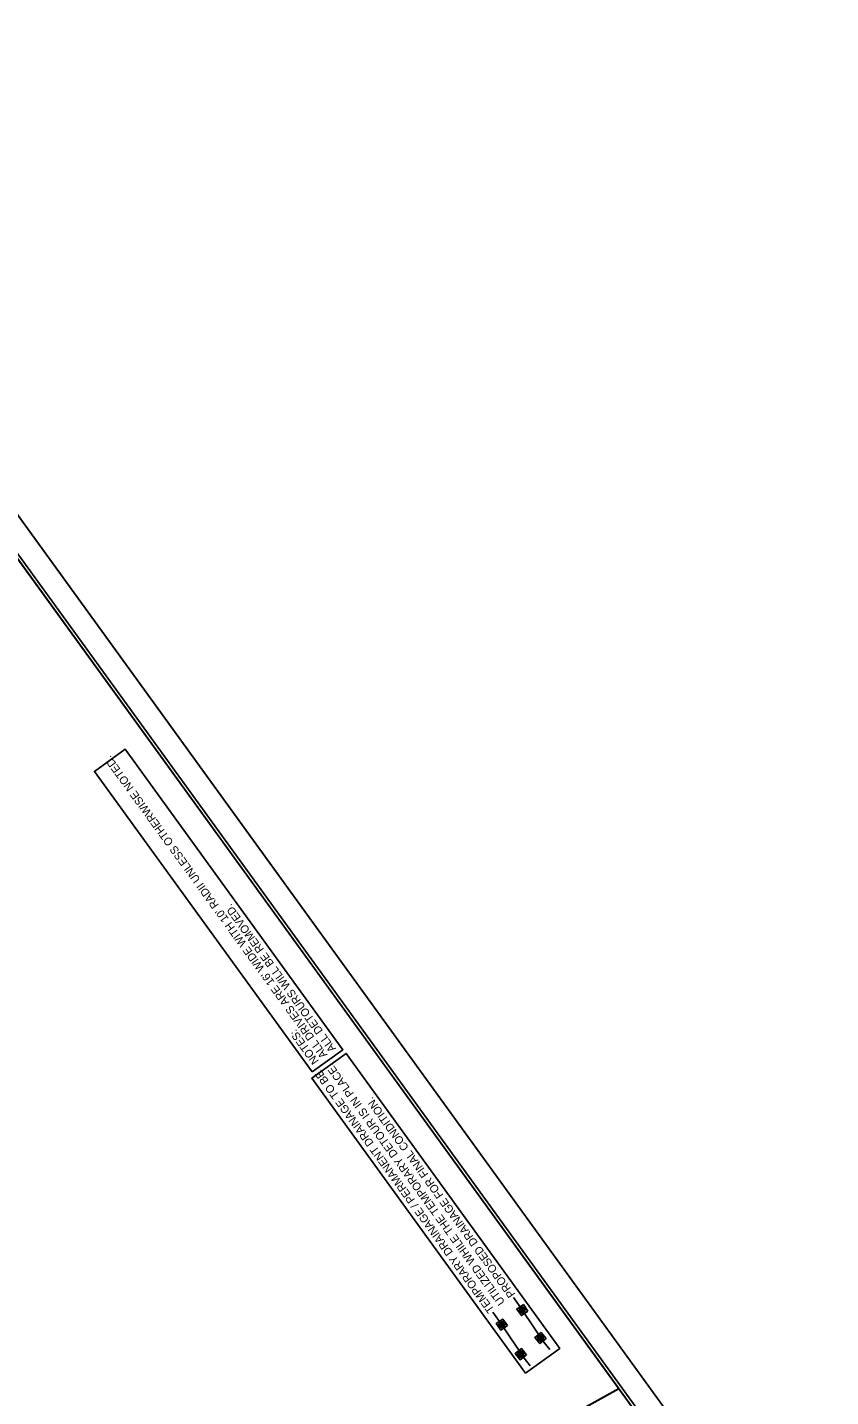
# Model space of a CAD drawing. Extents: x 474925 to 478950, y 494687 to 502905.
# Drawn here: x 476129 to 476832, y 501707 to 502905 of the extents above; entities that cross this region are included whole.
import ezdxf

# ---------------------------------------------------------------- set-up
doc = ezdxf.new("R2010")
doc.units = 0
for name, color, linetype in [('Old_Level_41', 7, 'Continuous'), ('Prop Drainage Structure CELL', 7, 'Continuous'), ('Prop DSN Text', 7, 'Continuous'), ('Prop Grid Mask', 7, 'Continuous'), ('Sheet Cutting Line CELL', 7, 'Continuous'), ('Sheet Data Field CELL', 7, 'Continuous'), ('Sheet Layout Plan Border', 7, 'Continuous'), ('Sheet Plan CELL', 7, 'Continuous'), ('Sheet Plan Layout CELL', 7, 'Continuous'), ('Sheet Plot Border Inside CELL', 7, 'Continuous'), ('Sheet Plot Border Outside CELL', 7, 'Continuous')]:
    doc.layers.add(name, color=color, linetype=linetype)

msp = doc.modelspace()

# ---------------------------------------------------------------- linework, layer by layer
at = {"layer": 'Old_Level_41'}
for p, q in [((476562.2, 501783.1), (476554.4, 501794)), ((476561.5, 501784), (476561.5, 501784)), ((476562.2, 501783.1), (476562.2, 501783.1)), ((476563.8, 501784.2), (476563.8, 501784.2)), ((476560.5, 501781.9), (476560.5, 501781.9)), ((476580.8, 501755.1), (476562.4, 501782.7)), ((476562.8, 501782.1), (476562.8, 501782.1)), ((476577.3, 501759.5), (476577.3, 501759.5)), ((476579.6, 501759.9), (476579.6, 501759.9)), ((476576.4, 501757.4), (476576.4, 501757.4)), ((476578, 501758.6), (476578, 501758.6)), ((476578.7, 501757.7), (476578.7, 501757.7)), ((476586.2, 501748.5), (476580.8, 501755.1))]:
    msp.add_line(p, q, dxfattribs=at)
for points in [[(476567, 501782.2), (476561.3, 501778.2), (476557.3, 501783.9), (476563, 501787.9)], [(476564.9, 501782.6), (476561.7, 501780.3), (476559.4, 501783.5), (476562.6, 501785.8)], [(476582.9, 501758.1), (476577.5, 501753.7), (476573.1, 501759.1), (476578.5, 501763.5)], [(476580.8, 501758.3), (476577.7, 501755.8), (476575.2, 501758.9), (476578.3, 501761.4)]]:
    msp.add_lwpolyline(points, close=True, dxfattribs=at)
for points in [[(476564.5, 501783.3), (476561.2, 501780.9), (476559.8, 501782.9), (476563.1, 501785.2), (476564.5, 501783.3)], [(476564.4, 501783.3), (476561.2, 501781), (476559.9, 501782.8), (476563.1, 501785.1), (476564.4, 501783.3)], [(476562.8, 501782.2), (476561.2, 501781.1), (476559.9, 501782.8), (476561.5, 501783.9), (476562.8, 501782.2)], [(476561, 501783), (476560.3, 501782.5), (476560.1, 501782.7), (476560.8, 501783.2), (476561, 501783)], [(476561.2, 501782.7), (476560.5, 501782.2), (476560.3, 501782.4), (476561, 501782.9), (476561.2, 501782.7)], [(476561.7, 501783.5), (476561, 501783), (476560.9, 501783.3), (476561.6, 501783.7), (476561.7, 501783.5)], [(476561.9, 501783.2), (476561.3, 501782.7), (476561.1, 501782.9), (476561.8, 501783.4), (476561.9, 501783.2)], [(476562.2, 501782.9), (476561.5, 501782.4), (476561.3, 501782.6), (476562, 501783.1), (476562.2, 501782.9)], [(476564.4, 501783.3), (476562.8, 501782.2), (476561.5, 501784), (476563.1, 501785.1), (476564.4, 501783.3)], [(476562.4, 501782.6), (476561.7, 501782.1), (476561.5, 501782.3), (476562.2, 501782.8), (476562.4, 501782.6)], [(476562.5, 501784.1), (476561.9, 501783.6), (476561.7, 501783.9), (476562.4, 501784.3), (476562.5, 501784.1)], [(476562.8, 501783.8), (476562.1, 501783.3), (476561.9, 501783.5), (476562.6, 501784), (476562.8, 501783.8)], [(476563, 501783.5), (476562.3, 501783), (476562.1, 501783.2), (476562.8, 501783.7), (476563, 501783.5)], [(476563.2, 501783.2), (476562.5, 501782.7), (476562.4, 501782.9), (476563.1, 501783.4), (476563.2, 501783.2)], [(476563.3, 501784.6), (476562.6, 501784.2), (476562.5, 501784.4), (476563.1, 501784.9), (476563.3, 501784.6)], [(476563.4, 501782.9), (476562.8, 501782.4), (476562.6, 501782.6), (476563.3, 501783.1), (476563.4, 501782.9)], [(476563.5, 501784.3), (476562.8, 501783.8), (476562.7, 501784.1), (476563.4, 501784.5), (476563.5, 501784.3)], [(476563.7, 501784), (476563.1, 501783.5), (476562.9, 501783.8), (476563.6, 501784.2), (476563.7, 501784)], [(476564, 501783.7), (476563.3, 501783.2), (476563.1, 501783.4), (476563.8, 501783.9), (476564, 501783.7)], [(476564.2, 501783.4), (476563.5, 501782.9), (476563.3, 501783.1), (476564, 501783.6), (476564.2, 501783.4)], [(476561.4, 501782.4), (476560.7, 501781.9), (476560.6, 501782.1), (476561.2, 501782.6), (476561.4, 501782.4)], [(476561.6, 501782), (476560.9, 501781.6), (476560.8, 501781.8), (476561.5, 501782.3), (476561.6, 501782)], [(476561.7, 501782), (476561, 501781.5), (476561.2, 501781.3), (476561.9, 501781.7), (476561.7, 501782)], [(476562.4, 501782.5), (476561.8, 501782), (476561.9, 501781.8), (476562.6, 501782.3), (476562.4, 501782.5)], [(476580.3, 501759), (476577.2, 501756.4), (476575.7, 501758.3), (476578.8, 501760.8), (476580.3, 501759)], [(476580.2, 501759), (476577.2, 501756.5), (476575.8, 501758.3), (476578.8, 501760.7), (476580.2, 501759)], [(476578.7, 501757.8), (476577.2, 501756.5), (476575.8, 501758.3), (476577.3, 501759.5), (476578.7, 501757.8)], [(476577.5, 501759), (476576.9, 501758.5), (476576.7, 501758.7), (476577.4, 501759.3), (476577.5, 501759)], [(476577.8, 501758.7), (476577.1, 501758.2), (476577, 501758.4), (476577.6, 501759), (476577.8, 501758.7)], [(476580.2, 501759), (476578.7, 501757.8), (476577.3, 501759.5), (476578.8, 501760.7), (476580.2, 501759)], [(476578.3, 501759.7), (476577.7, 501759.2), (476577.5, 501759.4), (476578.2, 501759.9), (476578.3, 501759.7)], [(476578.6, 501759.4), (476577.9, 501758.9), (476577.7, 501759.1), (476578.4, 501759.6), (476578.6, 501759.4)], [(476578.8, 501759.1), (476578.2, 501758.6), (476578, 501758.8), (476578.6, 501759.3), (476578.8, 501759.1)], [(476579, 501760.3), (476578.4, 501759.7), (476578.2, 501759.9), (476578.9, 501760.5), (476579, 501760.3)], [(476579, 501758.8), (476578.4, 501758.3), (476578.2, 501758.5), (476578.9, 501759), (476579, 501758.8)], [(476579.3, 501760), (476578.6, 501759.4), (476578.5, 501759.6), (476579.1, 501760.2), (476579.3, 501760)], [(476579.5, 501759.7), (476578.9, 501759.1), (476578.7, 501759.3), (476579.4, 501759.9), (476579.5, 501759.7)], [(476579.8, 501759.4), (476579.1, 501758.8), (476578.9, 501759), (476579.6, 501759.6), (476579.8, 501759.4)], [(476580, 501759.1), (476579.4, 501758.5), (476579.2, 501758.7), (476579.8, 501759.3), (476580, 501759.1)], [(476576.8, 501758.5), (476576.2, 501757.9), (476576, 501758.2), (476576.6, 501758.7), (476576.8, 501758.5)], [(476577.1, 501758.2), (476576.4, 501757.6), (476576.2, 501757.9), (476576.9, 501758.4), (476577.1, 501758.2)], [(476577.3, 501757.9), (476576.6, 501757.3), (476576.5, 501757.6), (476577.1, 501758.1), (476577.3, 501757.9)], [(476577.5, 501757.6), (476576.9, 501757), (476576.7, 501757.3), (476577.4, 501757.8), (476577.5, 501757.6)], [(476577.6, 501757.5), (476577, 501757), (476577.1, 501756.7), (476577.8, 501757.3), (476577.6, 501757.5)], [(476578, 501758.4), (476577.4, 501757.9), (476577.2, 501758.1), (476577.8, 501758.7), (476578, 501758.4)], [(476578.3, 501758.1), (476577.6, 501757.6), (476577.4, 501757.8), (476578.1, 501758.4), (476578.3, 501758.1)], [(476578.3, 501758.1), (476577.7, 501757.5), (476577.8, 501757.3), (476578.5, 501757.8), (476578.3, 501758.1)], [(476579.3, 501758.5), (476578.6, 501758), (476578.5, 501758.2), (476579.1, 501758.7), (476579.3, 501758.5)]]:
    msp.add_lwpolyline(points, dxfattribs=at)
at = {"layer": 'Prop Drainage Structure CELL'}
for p, q in [((476544.2, 501770.3), (476536.4, 501781.3)), ((476543.5, 501771.3), (476543.5, 501771.3)), ((476545.8, 501771.5), (476545.8, 501771.5)), ((476542.6, 501769.2), (476542.6, 501769.2)), ((476544.2, 501770.3), (476544.2, 501770.3)), ((476563.6, 501741), (476544.3, 501770.2)), ((476544.9, 501769.4), (476544.9, 501769.4)), ((476559.2, 501743.3), (476559.2, 501743.3)), ((476560, 501745.4), (476560, 501745.4)), ((476560.8, 501744.5), (476560.8, 501744.5)), ((476561.5, 501743.6), (476561.5, 501743.6)), ((476562.3, 501745.8), (476562.3, 501745.8)), ((476568.9, 501734.4), (476563.6, 501741))]:
    msp.add_line(p, q, dxfattribs=at)
for points in [[(476549.1, 501769.5), (476543.4, 501765.4), (476539.3, 501771.2), (476545, 501775.2)], [(476547, 501769.9), (476543.7, 501767.5), (476541.4, 501770.8), (476544.7, 501773.1)], [(476565.7, 501744), (476560.2, 501739.6), (476555.8, 501745), (476561.3, 501749.4)], [(476563.6, 501744.2), (476560.5, 501741.7), (476557.9, 501744.8), (476561.1, 501747.3)]]:
    msp.add_lwpolyline(points, close=True, dxfattribs=at)
for points in [[(476546.5, 501770.5), (476543.2, 501768.2), (476541.9, 501770.1), (476545.1, 501772.4), (476546.5, 501770.5)], [(476546.4, 501770.5), (476543.2, 501768.3), (476542, 501770.1), (476545.1, 501772.3), (476546.4, 501770.5)], [(476544.8, 501769.4), (476543.3, 501768.3), (476542, 501770.1), (476543.5, 501771.2), (476544.8, 501769.4)], [(476543.7, 501770.8), (476543.1, 501770.3), (476542.9, 501770.5), (476543.6, 501771), (476543.7, 501770.8)], [(476546.4, 501770.5), (476544.8, 501769.4), (476543.6, 501771.2), (476545.1, 501772.3), (476546.4, 501770.5)], [(476544.6, 501771.4), (476543.9, 501770.9), (476543.7, 501771.1), (476544.4, 501771.6), (476544.6, 501771.4)], [(476544.8, 501771.1), (476544.1, 501770.6), (476544, 501770.8), (476544.6, 501771.3), (476544.8, 501771.1)], [(476545, 501770.8), (476544.3, 501770.3), (476544.2, 501770.5), (476544.9, 501771), (476545, 501770.8)], [(476545.3, 501771.9), (476544.6, 501771.4), (476544.5, 501771.6), (476545.2, 501772.1), (476545.3, 501771.9)], [(476545.5, 501771.6), (476544.9, 501771.1), (476544.7, 501771.3), (476545.4, 501771.8), (476545.5, 501771.6)], [(476545.8, 501771.3), (476545.1, 501770.8), (476544.9, 501771), (476545.6, 501771.5), (476545.8, 501771.3)], [(476546, 501771), (476545.3, 501770.5), (476545.2, 501770.7), (476545.8, 501771.2), (476546, 501771)], [(476546.2, 501770.7), (476545.5, 501770.2), (476545.4, 501770.4), (476546.1, 501770.9), (476546.2, 501770.7)], [(476543, 501770.3), (476542.3, 501769.8), (476542.2, 501770), (476542.8, 501770.5), (476543, 501770.3)], [(476543.2, 501769.9), (476542.5, 501769.5), (476542.4, 501769.7), (476543.1, 501770.2), (476543.2, 501769.9)], [(476543.4, 501769.6), (476542.8, 501769.1), (476542.6, 501769.4), (476543.3, 501769.9), (476543.4, 501769.6)], [(476543.7, 501769.3), (476543, 501768.8), (476542.8, 501769.1), (476543.5, 501769.5), (476543.7, 501769.3)], [(476544, 501770.5), (476543.3, 501770), (476543.1, 501770.2), (476543.8, 501770.7), (476544, 501770.5)], [(476543.7, 501769.2), (476543.1, 501768.7), (476543.2, 501768.5), (476543.9, 501769), (476543.7, 501769.2)], [(476544.2, 501770.2), (476543.5, 501769.7), (476543.4, 501769.9), (476544, 501770.4), (476544.2, 501770.2)], [(476544.4, 501769.8), (476543.7, 501769.4), (476543.6, 501769.6), (476544.3, 501770.1), (476544.4, 501769.8)], [(476544.5, 501769.8), (476543.8, 501769.3), (476544, 501769.1), (476544.6, 501769.5), (476544.5, 501769.8)], [(476545.2, 501770.4), (476544.6, 501770), (476544.4, 501770.2), (476545.1, 501770.7), (476545.2, 501770.4)], [(476545.5, 501770.1), (476544.8, 501769.6), (476544.6, 501769.9), (476545.3, 501770.3), (476545.5, 501770.1)], [(476563, 501744.9), (476559.9, 501742.4), (476558.5, 501744.2), (476561.6, 501746.7), (476563, 501744.9)], [(476563, 501744.9), (476559.9, 501742.4), (476558.6, 501744.2), (476561.6, 501746.6), (476563, 501744.9)], [(476561.4, 501743.7), (476559.9, 501742.5), (476558.6, 501744.2), (476560.1, 501745.4), (476561.4, 501743.7)], [(476559.6, 501744.4), (476558.9, 501743.9), (476558.8, 501744.1), (476559.4, 501744.6), (476559.6, 501744.4)], [(476559.8, 501744.1), (476559.2, 501743.6), (476559, 501743.8), (476559.6, 501744.3), (476559.8, 501744.1)], [(476560.1, 501743.8), (476559.4, 501743.3), (476559.2, 501743.5), (476559.9, 501744), (476560.1, 501743.8)], [(476560.3, 501745), (476559.6, 501744.4), (476559.5, 501744.6), (476560.1, 501745.2), (476560.3, 501745)], [(476560.3, 501743.5), (476559.6, 501743), (476559.5, 501743.2), (476560.1, 501743.7), (476560.3, 501743.5)], [(476560.5, 501744.7), (476559.9, 501744.1), (476559.7, 501744.3), (476560.4, 501744.9), (476560.5, 501744.7)], [(476560.4, 501743.4), (476559.7, 501742.9), (476559.9, 501742.7), (476560.5, 501743.2), (476560.4, 501743.4)], [(476560.8, 501744.4), (476560.1, 501743.8), (476559.9, 501744), (476560.6, 501744.6), (476560.8, 501744.4)], [(476562.9, 501744.9), (476561.4, 501743.7), (476560.1, 501745.4), (476561.6, 501746.6), (476562.9, 501744.9)], [(476561, 501744.1), (476560.4, 501743.5), (476560.2, 501743.7), (476560.8, 501744.3), (476561, 501744.1)], [(476561.1, 501745.6), (476560.4, 501745.1), (476560.3, 501745.3), (476560.9, 501745.8), (476561.1, 501745.6)], [(476561.1, 501744), (476560.4, 501743.4), (476560.6, 501743.2), (476561.3, 501743.8), (476561.1, 501744)], [(476561.3, 501745.3), (476560.7, 501744.8), (476560.5, 501745), (476561.2, 501745.5), (476561.3, 501745.3)], [(476561.6, 501745), (476560.9, 501744.5), (476560.7, 501744.7), (476561.4, 501745.2), (476561.6, 501745)], [(476561.8, 501746.2), (476561.1, 501745.6), (476561, 501745.9), (476561.6, 501746.4), (476561.8, 501746.2)], [(476561.8, 501744.7), (476561.2, 501744.2), (476561, 501744.4), (476561.6, 501744.9), (476561.8, 501744.7)], [(476562, 501745.9), (476561.4, 501745.3), (476561.2, 501745.6), (476561.9, 501746.1), (476562, 501745.9)], [(476562, 501744.4), (476561.4, 501743.9), (476561.2, 501744.1), (476561.9, 501744.6), (476562, 501744.4)], [(476562.3, 501745.6), (476561.6, 501745), (476561.5, 501745.3), (476562.1, 501745.8), (476562.3, 501745.6)], [(476562.5, 501745.3), (476561.9, 501744.7), (476561.7, 501745), (476562.3, 501745.5), (476562.5, 501745.3)], [(476562.8, 501745), (476562.1, 501744.4), (476561.9, 501744.7), (476562.6, 501745.2), (476562.8, 501745)]]:
    msp.add_lwpolyline(points, dxfattribs=at)
at = {"layer": 'Prop Grid Mask'}
for points in [[(476378.3, 501991.4), (476187.8, 502254.4), (476214.7, 502273.9), (476405.2, 502010.8)], [(476564.9, 501727.9), (476378, 501985.9), (476408.1, 502007.7), (476594.9, 501749.6)]]:
    msp.add_lwpolyline(points, close=True, dxfattribs=at)
at = {"layer": 'Sheet Cutting Line CELL'}
msp.add_line((476831.7, 501496.8), (475844.4, 502860.4), dxfattribs=at)
at = {"layer": 'Sheet Layout Plan Border'}
for points in [[(476646.4, 501714.4), (476110.2, 502454.9), (476091.7, 502441.6), (476003.5, 502563.5), (475989.4, 502553.3), (475869.1, 502719.5), (475838.1, 502697), (475782.5, 502773.7), (475678.6, 502698.5), (475653, 502679.9), (475264.4, 502398.5), (475136.1, 502305.7), (475211, 502202.4), (475104.2, 502125.1), (475196.5, 501997.6), (475162.7, 501973.1), (475722, 501200.7)], [(476646.5, 501714.2), (476022, 502576.7), (475989.4, 502553.3), (475869.2, 502719.3), (475838.2, 502696.9), (475782.7, 502773.5), (475678.8, 502698.3), (475653.1, 502679.7), (475264.5, 502398.4), (475136.3, 502305.6), (475211.1, 502202.2), (475104.3, 502124.9), (475196.6, 501997.5), (475162.8, 501973), (475722.1, 501200.5)]]:
    msp.add_lwpolyline(points, close=True, dxfattribs=at)
at = {"layer": 'Sheet Plan CELL'}
for points in [[(474953, 502262.6), (475832.8, 501047.7), (476683.3, 501663.5), (475803.5, 502878.4)], [(476683.3, 501663.5), (475832.8, 501047.7), (475070.4, 502100.6), (475191.9, 502188.6), (475074.6, 502350.6), (475803.5, 502878.4)]]:
    msp.add_lwpolyline(points, close=True, dxfattribs=at)
at = {"layer": 'Sheet Plan Layout CELL'}
msp.add_lwpolyline([(475865.4, 501002.6), (476715.9, 501618.4), (475836.1, 502833.4), (475157, 502341.6), (475297.3, 502147.8), (475126, 502023.8)], close=True, dxfattribs=at)
at = {"layer": 'Sheet Plot Border Inside CELL'}
msp.add_lwpolyline([(476807.9, 501495.6), (475830.8, 502845), (474976.3, 502226.3), (475953.4, 500876.9)], close=True, dxfattribs=at)
at = {"layer": 'Sheet Plot Border Outside CELL'}
msp.add_lwpolyline([(475811.8, 502905.4), (476799.1, 501541.8), (475912.2, 500899.6), (474924.9, 502263.2)], close=True, dxfattribs=at)

# ---------------------------------------------------------------- texts
at = {"layer": 'Prop DSN Text'}
for s, p in [("ALL DRIVES ARE 16' WIDE WITH 10' RADII UNLESS OTHERWISE NOTED. ", (476391.8, 502006.5)), ('ALL DETOURS WILL BE REMOVED. ', (476399.3, 502011.9)), ('NOTES: ', (476384.4, 502001.1))]:
    msp.add_text(s, height=7, rotation=125.9074, dxfattribs=at).set_placement(p)
at = {"layer": 'Sheet Data Field CELL'}
for s, p in [('UTILIZED WHILE THE TEMPORARY DETOUR IS IN PLACE.', (476547.2, 501790.2)), ('TEMPORARY DRAINAGE / PERMANENT DRAINAGE TO BE ', (476538, 501783.6)), ('PROPOSED DRAINAGE FOR FINAL CONDITION.', (476556.2, 501797))]:
    msp.add_text(s, height=7, rotation=125.9074, dxfattribs=at).set_placement(p)

doc.saveas('drawing.dxf')
